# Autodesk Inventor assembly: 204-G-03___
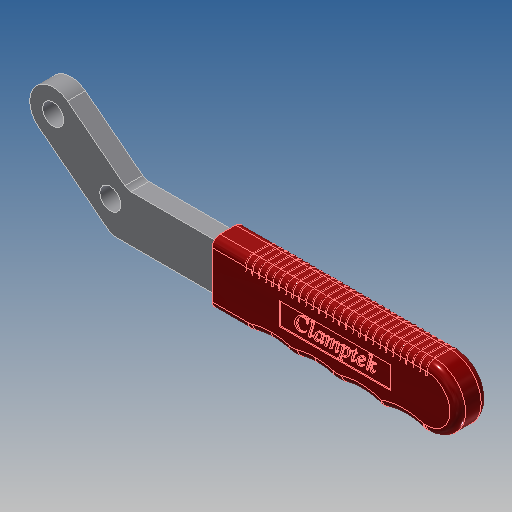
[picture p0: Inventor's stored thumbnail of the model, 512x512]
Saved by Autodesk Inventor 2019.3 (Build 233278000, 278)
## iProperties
Created: 2010-06
Part Number: 204-G-03___
Material: Ogólny
Document SubType Name: Assembly
Designer: CADENGINEERING4
Author: CADENGINEERING4
Revision Number: ANY
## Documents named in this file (3)
- E:\STRONA\Horizontal toggle clamp\CH-204-G\204-G-03___.iam
- E:\STRONA\Horizontal toggle clamp\CH-204-G\204-GB-03___.ipt
- E:\STRONA\Horizontal toggle clamp\CH-204-G\204-GB-07___.ipt
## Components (2 placed, 2 different names)
1. 204-GB-03_??_30
2. 204-GB-07_??_31
